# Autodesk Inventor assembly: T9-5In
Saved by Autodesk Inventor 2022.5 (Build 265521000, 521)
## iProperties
Created: 2024-07
Part Number: T9-5In
Document SubType Name: Assembly
Designer: AdminForWorker
Title: T9-5In v3
Author: AdminForWorker
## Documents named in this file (2)
- c:\worker\convert-fusion-r03-cosv3\tmp\job-1\63\temp\files\f0394d61-3fef-4993-9021-e7f535fc5560\T9-5In v3.iam
- c:\worker\convert-fusion-r03-cosv3\tmp\job-1\63\temp\files\f0394d61-3fef-4993-9021-e7f535fc5560\BU-T10-5-LED-120V.iam
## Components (1 placed, 1 different names)
1. BU-T10-5-LED-120V:1 [sub-assembly]
